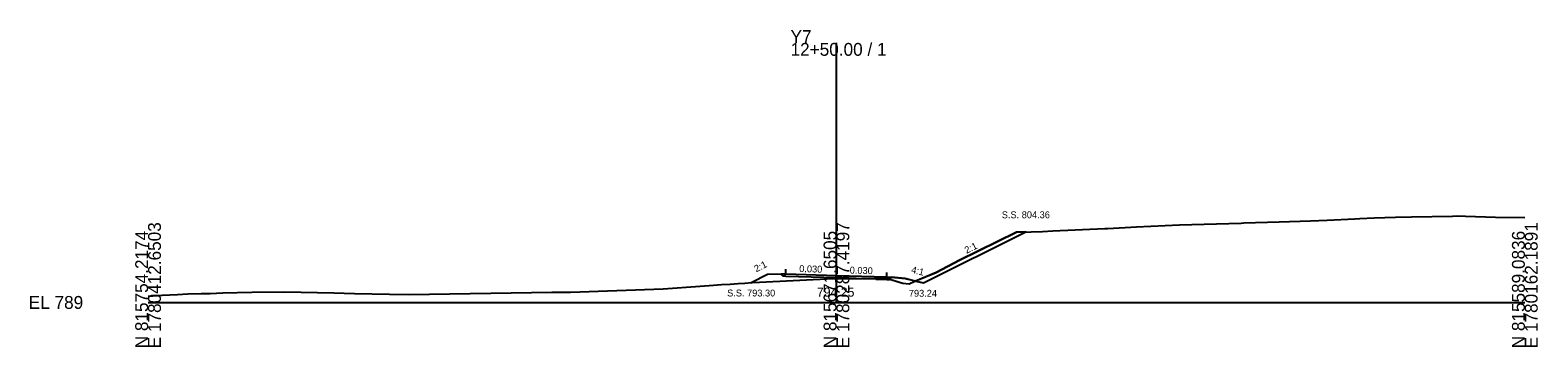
# Model space of a CAD drawing. Extents: x -26 to 2903, y -10 to 5536.
# Drawn here: x -25.7 to 302.8, y 2490.3 to 2559.4 of the extents above; entities that cross this region are included whole.
import ezdxf

# ---------------------------------------------------------------- set-up
doc = ezdxf.new("R2010")
doc.units = 0
for name, color, linetype in [('Exist Cross Section Cell', 7, 'Continuous'), ('Exist XS Center Line Elevation Label', 7, 'Continuous'), ('Exist XS Ground Line', 7, 'Continuous'), ('Prop XS Ditch Slope Text', 7, 'Continuous'), ('Prop XS Ditch Standard Text', 7, 'Continuous'), ('Prop XS Dump Level', 7, 'Continuous'), ('Prop XS Earthwork Shape', 7, 'Continuous'), ('Prop XS EOT Tick Mark', 7, 'Continuous'), ('Prop XS Finish Grade', 7, 'Continuous'), ('Prop XS Finish Grade Earthwork', 7, 'Continuous'), ('Prop XS Finish Grade Pavement', 7, 'Continuous'), ('Prop XS Pvmt Edge Slope', 7, 'Continuous'), ('Prop XS SE Text', 7, 'Continuous'), ('Prop XS Side Slope Text', 7, 'Continuous'), ('Prop XS SS Elevation Text', 7, 'Continuous'), ('Prop XS Subgrade Earthwork', 7, 'Continuous')]:
    doc.layers.add(name, color=color, linetype=linetype)

msp = doc.modelspace()

# ---------------------------------------------------------------- linework, layer by layer
at = {"layer": 'Exist Cross Section Cell'}
for p, q in [((150, 2500), (150, 2556.58)), ((0, 2500), (150, 2500)), ((150, 2500), (300, 2500))]:
    msp.add_line(p, q, dxfattribs=at)
at = {"layer": 'Exist XS Ground Line'}
for p, q in [((215.42, 2516.47), (224.75, 2516.91)), ((224.75, 2516.91), (238.21, 2517.31)), ((238.21, 2517.31), (238.74, 2517.33)), ((238.74, 2517.33), (246.49, 2517.58)), ((246.49, 2517.58), (253.31, 2517.8)), ((253.31, 2517.8), (256.95, 2517.96)), ((256.95, 2517.96), (262.94, 2518.22)), ((262.94, 2518.22), (264.02, 2518.3)), ((264.02, 2518.3), (267.14, 2518.43)), ((267.14, 2518.43), (271.83, 2518.62)), ((271.83, 2518.62), (275.33, 2518.69)), ((275.33, 2518.69), (284.27, 2518.81)), ((284.27, 2518.81), (285.38, 2518.86)), ((285.38, 2518.86), (287.1, 2518.82)), ((287.1, 2518.82), (293.6, 2518.58)), ((293.6, 2518.58), (300, 2518.55)), ((176.79, 2509.22), (189.24, 2515.32)), ((189.24, 2515.32), (192.44, 2515.39)), ((192.44, 2515.39), (194.91, 2515.45)), ((194.91, 2515.45), (197.13, 2515.6)), ((197.13, 2515.6), (208.47, 2516.13)), ((208.47, 2516.13), (209.15, 2516.15)), ((209.15, 2516.15), (215.42, 2516.47)), ((171.7, 2506.53), (176.79, 2509.22)), ((112.24, 2502.93), (120.31, 2503.55)), ((120.31, 2503.55), (123.21, 2503.75)), ((123.21, 2503.75), (124.99, 2503.88)), ((124.99, 2503.88), (126.83, 2504)), ((126.83, 2504), (128.6, 2504.12)), ((128.6, 2504.12), (130.03, 2504.22)), ((130.03, 2504.22), (131.57, 2504.31)), ((131.57, 2504.31), (133.21, 2504.43)), ((133.21, 2504.43), (149.38, 2505.25)), ((149.38, 2505.25), (150, 2505.25)), ((150, 2505.25), (156.14, 2505.25)), ((156.14, 2505.25), (157.54, 2505.25)), ((157.54, 2505.25), (158.59, 2505.27)), ((158.59, 2505.27), (160.6, 2505.36)), ((160.6, 2505.36), (164.48, 2504.21)), ((164.48, 2504.21), (165.87, 2504.07)), ((165.87, 2504.07), (167.09, 2504.6)), ((167.09, 2504.6), (171.7, 2506.53)), ((0, 2501.34), (3.09, 2501.58)), ((3.09, 2501.58), (6.41, 2501.75)), ((6.41, 2501.75), (8.67, 2501.88)), ((8.67, 2501.88), (11.57, 2501.95)), ((11.57, 2501.95), (13.51, 2501.96)), ((13.51, 2501.96), (16.28, 2502.08)), ((16.28, 2502.08), (22.59, 2502.21)), ((22.59, 2502.21), (29.44, 2502.31)), ((29.44, 2502.31), (33.38, 2502.23)), ((33.38, 2502.23), (40.48, 2502.08)), ((40.48, 2502.08), (44.96, 2501.98)), ((44.96, 2501.98), (52.58, 2501.83)), ((52.58, 2501.83), (56.86, 2501.72)), ((56.86, 2501.72), (87.95, 2502.2)), ((87.95, 2502.2), (90.82, 2502.21)), ((90.82, 2502.21), (92.08, 2502.26)), ((92.08, 2502.26), (112.24, 2502.93))]:
    msp.add_line(p, q, dxfattribs=at)
at = {"layer": 'Prop XS Dump Level'}
for p, q in [((139, 2506.22), (150, 2505.89)), ((150, 2505.89), (161, 2505.56))]:
    msp.add_line(p, q, dxfattribs=at)
at = {"layer": 'Prop XS Earthwork Shape'}
for points in [[(169, 2504.24), (191.25, 2515.36), (189.24, 2515.32), (176.79, 2509.22), (171.7, 2506.53), (167.26, 2504.67)], [(135, 2506.1), (131.41, 2504.3), (131.57, 2504.31), (133.21, 2504.43), (149.38, 2505.25), (150, 2505.25), (153.16, 2505.25), (150, 2505.35), (139, 2505.68), (138.47, 2505.69), (137.98, 2506.19)], [(158.59, 2505.09), (153.16, 2505.25), (156.14, 2505.25), (157.54, 2505.25), (158.59, 2505.27)], [(158.59, 2505.09), (158.59, 2505.27), (160.6, 2505.36), (161.62, 2505.06), (161.56, 2505), (161, 2505.02)], [(164.48, 2504.21), (165.87, 2504.07), (167.09, 2504.6), (167.26, 2504.67), (165, 2505.24), (162.03, 2505.47), (161.62, 2505.06)]]:
    msp.add_lwpolyline(points, close=True, dxfattribs=at)
at = {"layer": 'Prop XS EOT Tick Mark'}
for p, q in [((139, 2506.22), (139, 2507.22)), ((161, 2505.56), (161, 2506.56))]:
    msp.add_line(p, q, dxfattribs=at)
at = {"layer": 'Prop XS Finish Grade'}
for p, q in [((139, 2506.22), (137.98, 2506.19)), ((161, 2505.56), (162.03, 2505.47))]:
    msp.add_line(p, q, dxfattribs=at)
at = {"layer": 'Prop XS Finish Grade Earthwork'}
for p, q in [((169, 2504.24), (191.25, 2515.36)), ((135, 2506.1), (131.41, 2504.3)), ((137.98, 2506.19), (135, 2506.1)), ((162.03, 2505.47), (165, 2505.24)), ((165, 2505.24), (169, 2504.24))]:
    msp.add_line(p, q, dxfattribs=at)
at = {"layer": 'Prop XS Finish Grade Pavement'}
for p, q in [((139, 2506.22), (150, 2505.89)), ((150, 2505.89), (161, 2505.56))]:
    msp.add_line(p, q, dxfattribs=at)
at = {"layer": 'Prop XS Pvmt Edge Slope'}
for p, q in [((139, 2506.22), (138.47, 2505.69)), ((161, 2505.56), (161.56, 2505))]:
    msp.add_line(p, q, dxfattribs=at)
at = {"layer": 'Prop XS Subgrade Earthwork'}
for p, q in [((138.47, 2505.69), (137.98, 2506.19)), ((139, 2505.68), (138.47, 2505.69)), ((150, 2505.35), (139, 2505.68)), ((158.59, 2505.09), (150, 2505.35)), ((158.59, 2505.09), (158.59, 2505.27)), ((158.59, 2505.09), (158.59, 2505.27)), ((158.59, 2505.09), (161, 2505.02)), ((161, 2505.02), (161.56, 2505)), ((161.56, 2505), (162.03, 2505.47))]:
    msp.add_line(p, q, dxfattribs=at)

# ---------------------------------------------------------------- texts
at = {"layer": 'Exist Cross Section Cell'}
for s, p in [('Y7', (140, 2556.58)), ('12+50.00 / 1', (140, 2553.78)), ('EL 789', (-26, 2498.6))]:
    msp.add_text(s, height=2.8, dxfattribs=at).set_placement(p)
for s, p in [('E 1780412.6503', (2.8, 2490)), ('E 1780287.4197', (152.8, 2490)), ('E 1780162.1891', (302.8, 2490)), ('N 815754.2174', (0, 2490)), ('N 815671.6505', (150, 2490)), ('N 815589.0836', (300, 2490))]:
    msp.add_text(s, height=2.8, rotation=90, dxfattribs=at).set_placement(p)
at = {"layer": 'Exist XS Center Line Elevation Label'}
msp.add_text('794.25', height=2, dxfattribs=at).set_placement((145.74, 2501.25))
at = {"layer": 'Prop XS Ditch Slope Text'}
msp.add_text('4:1', height=1.5, rotation=345.9638, dxfattribs=at).set_placement((166.19, 2506.49))
at = {"layer": 'Prop XS Ditch Standard Text'}
msp.add_text('793.24', height=1.5, dxfattribs=at).set_placement((165.78, 2501.24))
at = {"layer": 'Prop XS Dump Level'}
for s, height, p in [('Case1', 0.04, (135, 2506.06)), ('Eop', 0.3, (158.59, 2504.97)), ('Eop', 0.3, (158.59, 2504.97)), ('Case1', 0.04, (165, 2505.2))]:
    msp.add_text(s, height=height, dxfattribs=at).set_placement(p)
at = {"layer": 'Prop XS SE Text'}
for p in [(141.88, 2506.63), (152.88, 2506.3)]:
    msp.add_text('0.030', height=1.5, rotation=358.2816, dxfattribs=at).set_placement(p)
at = {"layer": 'Prop XS Side Slope Text'}
for p in [(178.37, 2510.6), (132.53, 2506.54)]:
    msp.add_text('2:1', height=1.5, rotation=26.5651, dxfattribs=at).set_placement(p)
at = {"layer": 'Prop XS SS Elevation Text'}
for s, p in [('S.S. 804.36', (186.03, 2518.36)), ('S.S. 793.30', (126.18, 2501.3))]:
    msp.add_text(s, height=1.5, dxfattribs=at).set_placement(p)

doc.saveas('drawing.dxf')
